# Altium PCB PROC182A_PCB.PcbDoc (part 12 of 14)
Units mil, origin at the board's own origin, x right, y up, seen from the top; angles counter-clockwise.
Board outline 3168.31 x 3700.79 mil, 8 copper layers (Top Layer, L2_GND1, L3_SIG1, L4_PWR1, L5_PWR2, L6_SIG2, L7_GND2, Bottom Layer), stack 58.1 mil thick; 580 components, 391 nets, 8314 pads, 4370 vias.
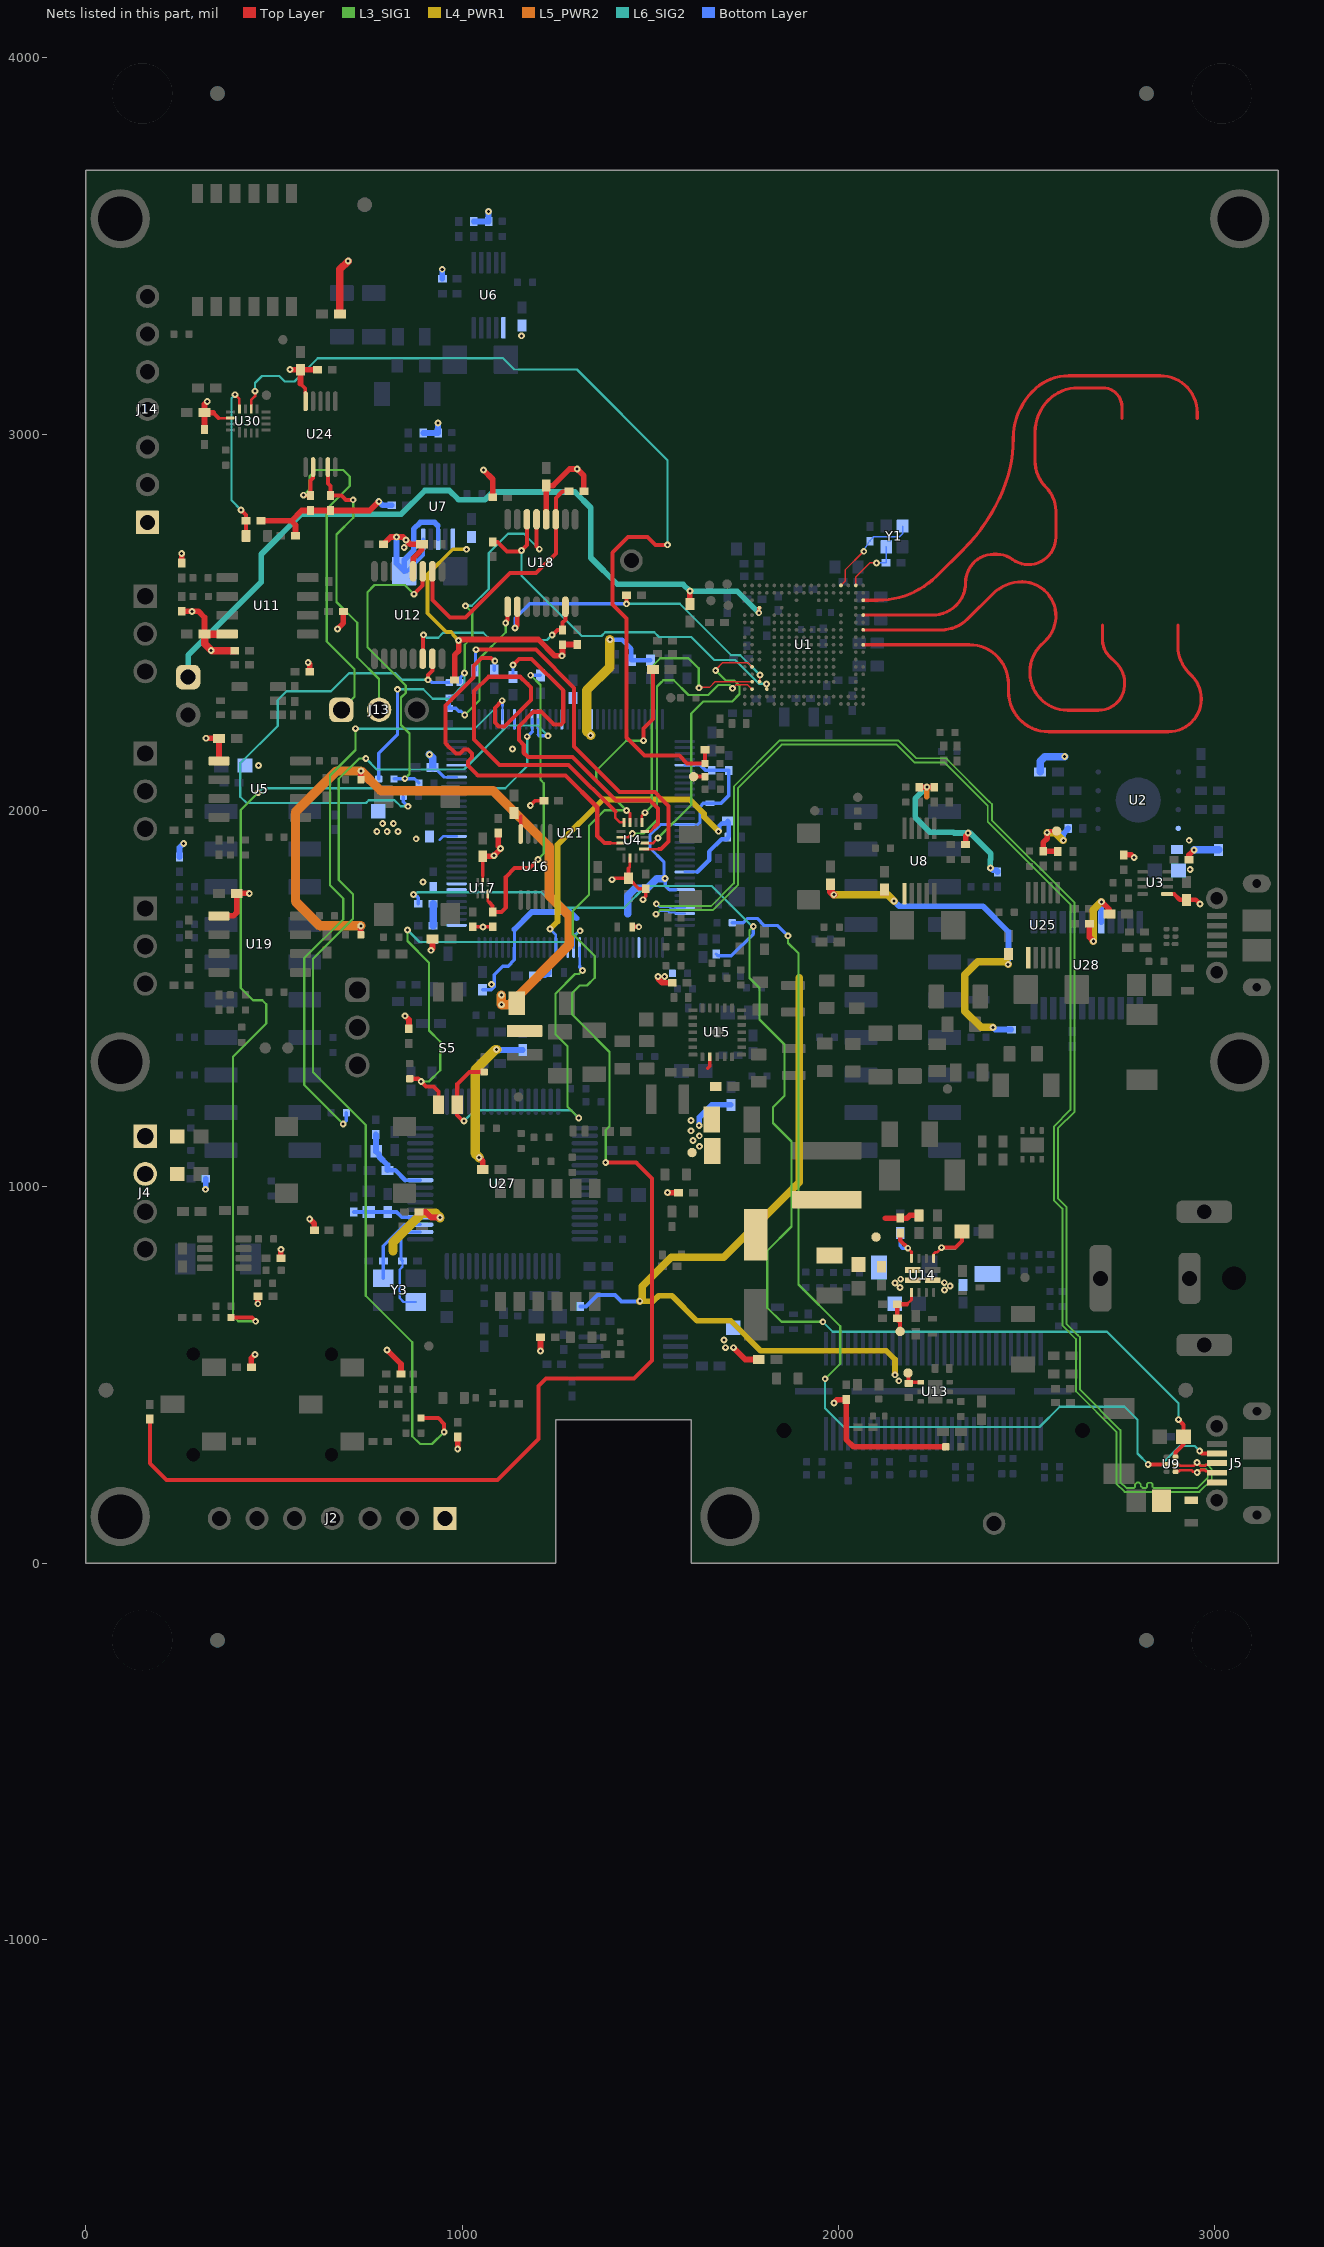
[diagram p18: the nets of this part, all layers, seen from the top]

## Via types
v1: diameter 13.77, hole 7, Top Layer to L2_GND1, tented both sides, 3444 vias
v2: diameter 18, hole 8, Top Layer to Bottom Layer, tented both sides, 911 vias
v3: diameter 13.77, hole 7, Top Layer to L2_GND1, tented top, 9 vias
v4: diameter 19.68, hole 7.87, Top Layer to Bottom Layer, 4 vias
v5: diameter 19.68, hole 7.87, Top Layer to Bottom Layer, tented both sides, 2 vias

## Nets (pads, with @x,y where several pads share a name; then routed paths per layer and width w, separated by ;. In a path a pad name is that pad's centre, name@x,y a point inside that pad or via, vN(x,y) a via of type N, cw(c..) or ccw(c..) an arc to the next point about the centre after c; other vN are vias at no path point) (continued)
SYS_RST_OUT: D9.1 R65.2 U30.12 | length 438.3
  Top Layer w7: v2(396.6,3104.72) 408.24,3093.09 U30.12@408.24,3066.34
  Top Layer w10.8: v2(412.68,2798.7) 426.03,2785.35 R65.2@426.03,2769.64 D9.1@426.03,2729.64
  L6_SIG2 w6: v2(396.6,3104.72) 387.21,3095.33 387.21,2824.17 v2(412.68,2798.7)
SYS_RST_OUT_SPIB_CS0_N: R146.1 R268.2 U30.10 | length 2497.9
  Top Layer w7: U30.10@439.74,3066.34 439.74,3090.48 450.04,3100.79 v2(450.04,3114.12)
  Top Layer w10.8: v2(1545.94,2706.01) 1545.67,2705.74 1513.3,2705.74 1492.75,2726.29 1440.94,2726.29 1399.63,2684.98 1399.63,2547.42 1436.63,2510.42 1436.63,2194.16 1484.92,2145.88 1576.88,2145.88 1597.72,2125.04 R268.2@1644.95,2125.04 1644.95,2160.46 R146.1@1645.54,2161.05
  L6_SIG2 w6: v2(450.04,3114.12) 450.04,3136.22 468.5,3154.67 514.07,3154.67 529.06,3139.68 554.81,3139.68 616.69,3201.57 1108.52,3201.57 1138.63,3171.47 1305.25,3171.47 1545.94,2930.78 v2(1545.94,2706.01)
TX1: U1.A3 | length 1302.5
  Top Layer w8.39: U1.A3@2065.55,2558.75 2104.39,2558.75 2104.45,2558.75 ccw(c2104.57,2780.67) 2202.13,2581.34 ccw(c2104.57,2780.67) 2261.61,2623.87 2332.43,2694.68 ccw(c1992.75,3034.6) 2436.7,2850.66 ccw(c2103.08,2988.89) 2464.2,2988.91 ; 2464.2,2988.94 cw(c2639.26,2989.49) 2515.1,3112.9 cw(c2611.78,3023.97) 2611.75,3155.33 2854.82,3155.33 ; 2854.86,3155.33 cw(c2854.83,3057.16) 2952.99,3057.16 2952.99,3042.46
TX2: U1.A5 | length 1302
  Top Layer w8.39: U1.A5@2065.55,2519.38 2249.63,2519.38 ccw(c2249.67,2608.28) 2312.64,2545.52 ccw(c2252.26,2605.7) 2337.51,2605.96 ; 2337.51,2606 cw(c2412.3,2605.95) 2412.3,2680.74 cw(c2419.35,2608.43) 2461.73,2667.45 2461.9,2667.32 ccw(c2504.65,2726.19) 2577.41,2726.19 2577.41,2795.68 ccw(c2488.67,2795.59) 2551.42,2858.34 cw(c2621.94,2928.86) 2522.21,2928.86 2522.21,3004.77 cw(c2642.88,3005.02) 2557.52,3090.31 cw(c2636.53,3011.27) 2636.53,3123.03 2701.8,3123.03 ; 2702.18,3123.02 cw(c2702.18,3072.21) 2752.99,3072.21 2752.99,3042.46
TX3: U1.A7 | length 1302.8
  Top Layer w8.39: U1.A7@2065.55,2480.01 2272.62,2480.01 ccw(c2272.62,2580.01) 2343.33,2509.3 2409.14,2575.11 cw(c2488.58,2495.74) 2487.84,2608.03 cw(c2487.9,2599.65) 2488.03,2608.03 cw(c2486.09,2516.69) 2547.32,2448.88 2545.91,2447.61 2537.63,2439.33 ccw(c2608.34,2368.62) 2520.31,2416.07 ccw(c2608.34,2368.62) 2508.44,2372.95 2508.44,2366.57 ccw(c2608.44,2366.57) 2510.83,2344.82 ccw(c2608.44,2366.57) 2608.44,2266.57 2690.85,2266.57 ; 2690.89,2266.57 ccw(c2690.94,2335.76) 2760.03,2339.57 2759.94,2341.29 ccw(c2691.24,2341.01) 2739.82,2389.58 2718.25,2411.15 cw(c2758.43,2451.33) 2701.6,2451.33 2701.6,2493
TX4: U1.A9 | length 1302.6
  Top Layer w8.39: U1.A9@2065.55,2440.64 2347.41,2440.64 cw(c2347.41,2336.43) 2451.62,2336.43 2451.62,2315.93 ccw(c2558.21,2315.93) 2558.21,2209.34 2875.9,2209.34 2875.95,2209.34 ccw(c2876.03,2296.96) 2938.61,2358.28 ; 2901.6,2493 2901.6,2436.72 ccw(c3001.6,2436.72) 2930.89,2366.01 2938.59,2358.31
UARTB_RX: J13.2 R275.1 U24.4 | length 766.4
  Top Layer w10.8: U24.4@643.35,2912.24 643.35,2868.98 649.99,2862.34 R275.1@649.99,2836.81 ; R275.1@650.21,2836.59 679.9,2836.59 690.9,2825.59 v2(710.5,2825.59)
  L3_SIG1 w6: v2(710.5,2825.59) 710.5,2777.81 665.97,2733.29 665.97,2554.06 721.39,2498.65 721.39,2407.64 779.43,2349.6 J13.2@779.43,2267.59
UARTB_TX: J13.1 R274.1 U24.2 | length 966.5
  Top Layer w10.8: v2(578.51,2837.87) 579.16,2837.23 594.55,2837.23 R274.1@597.17,2834.62 ; R274.1@597.17,2836.59 597.17,2876.67 604.01,2883.5 U24.2@604.01,2912.26
  L3_SIG1 w6: v2(578.51,2837.87) 595.34,2854.7 595.34,2889.02 611.13,2904.81 683.9,2904.81 701.46,2887.26 701.46,2862.43 640.38,2801.36 640.38,2449.39 714.25,2375.51 714.25,2302.42 J13.1@679.43,2267.59
USB_5V: C86.2 J5.1 L9.1
VBAT: J4.2 R32.1
VBUS_1_DETECT: C118.2 R236.1 R239.2 U21.1 | length 61.4
  Bottom Layer w8.7: C118.2@922.79,1693.47 C118.2@924.55,1695.23
  Bottom Layer w20: C118.2@922.79,1693.47 R236.1@922.79,1752.47
VCC_3V3: C34.1 C35.2 C36.1 C38.2 C40.1 C41.1 C52.2 C56.1 C57.1 C58.1 C59.1 C65.1 C104.1 C107.1 C109.2 C133.1 C135.1 C136.1 J2.1 J14.1 L14.2 R2.2 R5.2 R7.2 R8.2 R12.1 R14.2 R17.2 R22.2 R28.2 R44.2 R49.2 R50.1 R64.2 R65.1 R70.2 R82.2 R91.2 R94.1 R95.2 R97.2 R98.2 R99.2 R104.2 R105.2 R106.2 R107.2 R112.1 R115.1 R123.2 R127.2 R128.2 R135.2 R136.2 R138.2 R141.2 R142.1 R147.1 R149.1 R151.1 R154.2 R156.2 R157.2 R161.2 R163.2 R164.2 R165.2 R166.2 R172.2 R173.2 R200.1 R204.2 R207.2 R213.2 R253.2 R258.2 R262.2 R271.2 R274.2 R275.2 R277.2 R279.2 R283.1 R287.2 TP17.1 U2.8 U3.1 U4.14 U5.5 U6.6 U7.6 U7.8 U7.10 U8.6 U11.8 U12.12 U16.10 U17.5 U18.12 U19.5 U24.10 U25.6 U28.8 U30.14 | length 7795.7
  Top Layer w6.5: U17.5@1054.8,1809.55 1054.8,1826.78
  Top Layer w7: 353.08,3042.72 U30.14@384.62,3042.72 ; 1441.72,1845.84 1445.71,1849.83 U4.14@1445.71,1873.86
  Top Layer w8: 1054.8,1826.78 C52.2@1054.8,1878.55
  Top Layer w10: 570.67,3133.69 583.17,3121.18 583.17,3109.77 584.32,3108.62 U24.10@584.32,3087.46 ; R123.2@1028.35,1691.39 R138.2@1081.26,1691.39 ; U16.10@1155.59,1937.85 1155.59,1983.88 ; v2(1181.1,2013.78) 1193.57,2026.25 R95.2@1217.06,2026.25 ; v2(1398.42,1816.25) 1400.58,1816.25 1404.35,1820.02 C40.1@1441.72,1820.02 ; 1441.72,1845.84 C40.1@1441.72,1820.02 ; v2(1480.6,1763.15) 1480.6,1765.3 1487.66,1772.35 R5.2@1487.66,1792.41 1469.33,1792.41 C40.1@1441.72,1820.02 ; v2(2554.38,1941.12) 2556.54,1941.12 2561.07,1945.65 TP17.1@2579.58,1945.65 ; U3.1@2872.92,1778.17 2891.33,1778.17
  Top Layer w10.8: 338.66,3057.13 353.08,3042.72
  Top Layer w12: 2891.33,1778.17 2906.81,1762.7 C36.1@2924.66,1762.7 2949.49,1762.7 v2(2960.1,1752.09)
  Top Layer w15: R97.2@254.77,2529.42 v2@282.35,2529.42 ; R98.2@254.77,2657.7 254.77,2682.89 v2(255.07,2683.18) ; v2(282.56,2529.21) v2@282.35,2529.42 ; C65.1@315.62,2468.79 315.42,2468.99 315.42,2513.32 299.32,2529.42 v2@282.35,2529.42 ; R271.2@315.66,3012.1 C136.1@315.66,3057.1 ; v2(319.74,2192.12) 319.88,2191.99 354.05,2191.99 C38.2@354.18,2191.85 U5.5@354.18,2131.85 ; v2(322.86,3086.49) 315.66,3079.29 C136.1@315.66,3057.1 ; 338.66,3057.13 C136.1@315.68,3057.13 ; U19.5@354.01,1720.14 392.47,1720.14 401.26,1728.93 C109.2@401.26,1780.14 434.36,1780.14 v2(434.5,1780) ; R204.2@440.06,520.9 440.06,545.37 v2(449.8,555.12) ; v2(457.16,689.73) 457.42,689.99 457.42,709.08 R22.2@457.67,709.34 ; R65.1@465.4,2769.64 546.41,2769.64 ; R17.2@518.5,810.73 518.5,834.19 v2(518.57,834.26) ; v2(542.61,3171.73) 542.97,3171.37 570.31,3171.37 C135.1@570.67,3171.01 ; R64.2@557.48,2729.64 557.48,2758.57 546.41,2769.64 ; 570.67,3133.69 C135.1@570.67,3171.01 ; v2(591.03,2393.29) 591.03,2392.48 595.04,2388.47 R82.2@595.04,2369.21 ; v2(595.09,914.75) 607.39,902.45 607.39,886.97 607.46,886.9 R287.2@607.46,884.63 ; R253.2@615.67,3171.01 C135.1@570.67,3171.01 ; v2(668.89,2482.57) 684.58,2498.26 684.58,2526.44 R161.2@684.56,2528.79 ; v2(778.64,2821.3) 754.55,2797.22 R275.2@650.21,2797.22 R274.2@597.17,2797.22 573.98,2797.22 546.41,2769.64 ; R7.2@791.59,2707.74 810.53,2726.68 842.92,2726.68 851.01,2718.59 v2(851.1,2718.59) 862.11,2707.58 C41.1@892.99,2707.58 892.99,2693.18 869.69,2669.88 U12.12@869.69,2635.52 ; v2(800.64,566.66) 837.74,529.56 R207.2@837.74,503.14 ; v2(848.28,1454.6) 858.69,1444.19 R164.2@858.69,1420.46 ; R165.2@885.92,933.61 903.28,933.61 918.12,918.77 v2(941.29,918.77) ; v2(917.32,1628.63) 917.32,1629.44 921.46,1633.58 R213.2@921.46,1658.85 ; R8.2@979.95,2346.78 979.95,2413.12 990.66,2423.83 v2(990.66,2452.12) ; R28.2@988.19,335.63 R28.2@988.19,335.63 988.25,303.82 v2(988.3,303.76) ; v2@990.09,2452.69 v2(990.66,2452.12) ; v2(1045.47,1078.08) 1054.8,1068.75 R70.2@1054.8,1046.11 ; C52.2@1054.8,1878.55 1081.85,1878.55 1083.55,1880.24 v2(1084.36,1880.24) 1084.36,1880.93 1101.79,1898.36 1101.79,1899.86 1096.4,1905.26 R163.2@1096.4,1939.9 ; v2(1057.02,2904.62) 1081.36,2880.28 R127.2@1081.36,2832.49 ; v2(1208.11,564.42) R141.2@1208.07,600.82 ; U18.12@1223.27,2773.84 1223.27,2863.03 C107.1@1223.43,2863.19 1241.5,2863.19 1285.66,2907.34 v2(1305.73,2907.34) 1323.43,2889.64 R149.1@1323.43,2847.79 ; v2(1265.58,2411.26) 1245.7,2411.26 1202.51,2454.45 993.8,2454.45 991.47,2452.12 v2(990.66,2452.12) ; v2@1266.79,2413.33 1266.79,2440.45 1267.35,2441.03 R128.2@1306.31,2441.03 ; v2(1520.14,1558.91) 1520.71,1558.34 1520.71,1553 1531.3,1542.41 1544.97,1542.41 1545.31,1542.75 L14.2@1558.38,1542.75 ; v2(1545.45,985.09) 1560.29,985.09 1560.91,984.47 R172.2@1575.22,984.47 ; v2(1987.89,426.38) 1987.89,427.33 1995.6,435.04 R258.2@2020.2,435.04 2020.2,329.4 2039.8,309.8 R91.2@2284.82,309.8 ; R115.1@2214.61,2061.87 2214.8,2062.06 2234.24,2062.06 v2(2234.43,2062.26) ; v2@2234.25,2061.87 R107.2@2253.97,2061.87 ; R106.2@2337.61,1909.92 2337.61,1932.85 2344.35,1939.59 v2(2344.35,1940.4) ; v2@2554.56,1940.94 2554.56,1926.01 2543.66,1915.11 R142.1@2543.66,1891.83 2543.46,1891.62 R136.2@2582.83,1891.62 ; R135.2@2666.46,1699.68 2666.46,1663.59 v2(2677.26,1652.79) ; v2@2698.87,1757.66 2719.44,1737.08 C56.1@2719.44,1725.45 ; R151.1@2757.43,1882.19 2777.86,1882.19 2784.63,1875.41 v2(2785.44,1875.41) ; R283.1@2931.06,1869.68 2931.06,1881.8 v2(2944.81,1895.56)
  Top Layer w20: U11.8@375.62,2468.79 C65.1@315.62,2468.79 315.62,2443.36 v2(333.48,2425.5) 334.74,2424.24 R157.2@395.99,2424.24 ; R277.2@675.36,3319.65 675.36,3437.81 v2(697.24,3459.69) ; R262.2@1979.05,1804.31 1979.05,1784.89 v2(1987.54,1776.4)
  L5_PWR2 w15: 2234.43,2036.96 v2(2234.43,2062.26)
  L4_PWR1 w10: v2(990.66,2452.12) 976.55,2466.23 976.55,2468.45 970.69,2474.31 958.07,2474.31 908.07,2524.31 908.07,2626.93 975.31,2694.18 v2(1011.63,2694.18)
  L4_PWR1 w20: v2(1987.54,1776.4) 2130.61,1776.4 v2(2147.47,1759.53) ; v2(2410.16,1423.76) 2378.89,1423.76 2335.86,1466.79 2335.86,1564.17 2370.02,1598.32 2444,1598.32 v2(2450.79,1591.54) ; v2(2554.38,1941.12) 2576.02,1941.12 2596.2,1920.94 v2(2597.08,1920.94) ; v2(2677.26,1652.79) 2677.26,1736.62 v2(2698.3,1757.66)
  L4_PWR1 w25: 816.39,830.44 816.39,853.02 893.41,930.04 930.02,930.04 v2(941.29,918.77) ; v2(1045.47,1078.08) 1034.33,1089.22 1034.33,1310.79 1088.69,1365.16 1091.42,1365.16 v2(1091.54,1365.28)
  L6_SIG2 w15: v2(2234.43,2062.26) 2203.96,2031.79 2203.96,1981.53 2243.28,1942.21 2305.35,1942.21 2307.15,1940.4 v2(2344.35,1940.4) ; v2@2349.36,1941.23 2404.48,1886.11 2404.48,1871.11 2403.51,1870.14 v2(2403.51,1847.11)
  Bottom Layer w10: R200.1@852.95,2635.41 868.81,2651.26 896.69,2679.15 U7.10@896.69,2720.53 ; 935.32,2757.08 936.14,2756.26 936.14,2720.61 U7.8@936.06,2720.53
  Bottom Layer w15: R156.2@249.2,1876.82 249.2,1901.52 260.03,1912.35 v2(260.33,1912.35) ; v2(318.38,993.72) 318.65,994 318.65,1021.82 R166.2@318.93,1022.1 ; v2(778.64,2821.3) 788.76,2811.18 R104.2@813.05,2811.18 ; v2(825.71,2726.68) 825.71,2656.74 R200.1@846.26,2636.19 846.26,2666.04 871.16,2690.94 871.16,2747.75 889.03,2765.61 926.79,2765.61 935.32,2757.08 ; R105.2@896.69,3003.13 R112.1@936.06,3003.13 935.85,3003.34 v2(935.85,3029.84) ; v2(947.2,3437.99) 947.33,3437.85 947.33,3413.1 R2.2@947.46,3412.97 ; R14.2@1031.09,3564.92 R94.1@1070.46,3564.92 1070.26,3565.13 v2(1070.26,3591.63) ; v2(1091.54,1365.28) 1092.35,1365.28 1093.64,1363.99 1156.75,1363.99 R99.2@1161.06,1363.98 ; v2(2147.47,1759.53) 2161.16,1745.84 2383.62,1745.84 2451.64,1677.83 2451.64,1635.51 2450.79,1634.66 v2(2450.79,1591.54) ; v2(2403.51,1847.11) 2404.32,1847.11 2410.3,1841.13 2420.01,1841.13 2422.35,1838.79 R173.2@2422.35,1836.82 ; v2(2410.16,1423.76) 2410.62,1423.76 2416.22,1418.15 R12.1@2459.19,1418.15 ; v2(2597.08,1920.94) 2597.08,1934.19 2596.28,1934.99 2596.28,1937.12 2607.44,1948.28 2607.44,1950.25 R50.1@2609.78,1952.59 ; U28.8@2698.32,1703.39 v2(2698.3,1757.66)
  Bottom Layer w20: R44.2@2535.44,2102.59 2535.44,2131.08 2547.9,2143.55 v2(2600.75,2143.55) ; v2(2944.81,1895.56) 2945.03,1895.35 R49.2@3009.77,1895.35
  other v2: 1538.14,1558.91 1055.39,1690.93 2934.26,1843.64 1101.79,1899.05 2931.64,1920.9 459.18,2119.6 846.05,2698.8 1157.51,3261.37
VCC_12V: C30.1 C49.1 C54.1 C60.1 L1.2 R4.2 R9.1 TP7.1 U14.7 | length 92
  Top Layer w15: 2124.85,917.07 2181.72,917.07 2189.19,924.54 R4.2@2213.72,924.54
VCC_CAN_3V3: C72.2 L4.2 R69.2 R129.2 | length 1840.8
  Top Layer w15: R129.2@730.9,1670.14 v2(730.9,1693.46) ; R69.2@731.07,2081.85 v2(731.1,2105.19)
  L5_PWR2 w25: v2(730.9,1693.46) 622.61,1693.48 557.42,1758.68 557.42,1996.06 666.55,2105.19 v2(731.1,2105.19) 783.75,2052.54 1082.35,2052.54 1231.24,1903.64 1231.24,1773.35 1284.22,1720.37 1284.22,1642.49 1126.03,1484.29 v2(1104.85,1484.29) 1104.18,1484.96 v2(1104.18,1509.73)
VCC_XDS_3V3: C105.1 C106.2 C108.1 C113.2 C114.1 C115.1 C116.2 L7.1 R195.2 R196.2 R202.1 R231.2 R233.2 TP20.1 U13.1 U21.7 U21.8 U21.16 U21.26 U21.28 U21.39 U21.47 U21.51 U21.52 U21.69 U21.79 U21.90 U21.101 U21.113 U21.122 | length 4050.1
  Top Layer w10: C105.1@2186.43,478.03 2189.73,481.33 U13.1@2218.4,481.33
  Top Layer w10.8: TP20.1@2184.58,505.88 2186.43,504.03 C105.1@2186.43,478.03
  Top Layer w12: C108.1@1451.68,1690.92 1451.82,1691.06 1469.28,1691.06 v2(1469.42,1691.2)
  L4_PWR1 w15: v2(1471.95,696.59) 1508,696.59 1522.31,710.9 1557.54,710.9 1624.2,644.24 1713.87,644.24 1793.42,564.69 2127.04,564.69 2149.87,541.85 v2(2149.87,500.99)
  L4_PWR1 w20: v2(1471.95,696.59) 1478.7,703.34 1478.7,736.35 1555.06,812.7 1695.11,812.7 1895.31,1012.89 1895.31,1556.44
  L4_PWR1 w25: v2(1341.6,2199.82) 1330.74,2210.68 1330.74,2319.46 1392.63,2381.35 v2(1392.63,2454.02)
  Bottom Layer w6: 1542.21,1962.84 U21.79@1591.56,1962.84 ; U21.79@1591.66,1962.94 1625.68,1962.94 ; U21.69@1591.66,2120.42 1633.4,2120.36
  Bottom Layer w7: 940.54,1922.34 949.65,1931.45 U21.16@985.36,1931.45 ; 952.17,2088.93 U21.26@985.36,2088.93 ; U21.39@1138.9,2219.16 U21.39@1138.9,2242.47
  Bottom Layer w8: U21.113@1280.63,1636.17 1280.63,1680.3
  Bottom Layer w8.7: C106.2@937.12,2103.97 952.17,2088.93 ; U21.122@1138.9,1636.17 1138.9,1684.26 ; 1280.63,1680.3 1291.29,1690.95 ; v2@1536.24,1819.4 1536.24,1863.41 1499.11,1900.54 1499.11,1935.72 1526.23,1962.84 1542.21,1962.84 ; v2(1538.71,1819.4) 1540,1818.11 1540,1800.42 1550.65,1789.78 U21.90@1568.45,1789.78 ; 1625.68,1962.94 1632.04,1969.3 1632.04,2010.7 1640.58,2019.25 C114.1@1658,2019.25
  Bottom Layer w9: R233.2@1054.62,1524.36 1077.65,1524.36 1085.43,1532.14 1085.43,1563.79 1108.32,1586.68 1122.43,1586.68 1138.9,1603.16 U21.122@1138.9,1636.17
  Bottom Layer w10: L7.1@1313.51,682.66 1329.36,682.66 1359.46,712.76 1406.49,712.76 1423.74,695.51 1470.87,695.51 v2(1471.95,696.59) ; 1633.4,2120.36 1646.78,2106.97 R231.2@1663.56,2106.97 1708.2,2106.96 1708.21,2039.85 1687.61,2019.25 C114.1@1658,2019.25
  Bottom Layer w12: v2(1392.63,2454.02) 1425.34,2454.02 1449.62,2429.74 R196.2@1449.62,2399.25 R195.2@1500.19,2399.25
  Bottom Layer w15: 1138.9,1684.26 1184.98,1730.35 1287.6,1730.35 1304.03,1713.91
  Bottom Layer w20: v2(913.04,2149.22) 921.53,2140.74 C106.2@921.53,2114.19 ; 1439.63,1725.39 1439.63,1773.25 1459.91,1793.53 1491.7,1793.53 1516.68,1818.51 1537.81,1818.51 v2(1538.71,1819.4)
  other v2: 2160.05,485 1077.76,1538.38 896.07,1810.38 877.94,1925.03 1134.18,2163.28
VDDC_1: C124.1 C125.2 C126.2 C127.1 U21.87 U21.115 | length 1177.5
  L4_PWR1 w15: v2(1233.78,1685.06) 1253.55,1704.83 1253.55,1909.06 1374.02,2029.53 1604.58,2029.53 1615.32,2018.79 1642.69,1991.42 1642.69,1983.63 v2(1681.38,1944.95)
  Bottom Layer w7: v2(1233.78,1685.06) 1249.14,1669.7 U21.115@1249.14,1636.17 ; 1245.8,1599.6 1249.14,1602.94 U21.115@1249.14,1636.11 ; U21.87@1591.66,1836.96 1625.07,1836.96
  Bottom Layer w12: C126.2@1193.75,1560.97 1221.46,1560.97 1224.8,1564.32 1229.3,1564.32 1230.8,1565.82 1230.8,1583 1247,1599.19 ; 1625.07,1836.96 1655.98,1867.87 1655.98,1891.07 1689.13,1924.22 1703.06,1924.22 1705.92,1927.08 C124.1@1705.92,1929.29 1708.7,1932.07 1708.7,1969.34 C125.2@1705.63,1972.41 1699.82,1966.6 1690.84,1966.6 1682.53,1958.28 1682.53,1946.1 v2(1681.38,1944.95)
VIN1_PR1: R9.2 R23.2 U14.6 | length 136.9
  Top Layer w7: v2(2184.16,837.42) 2193.8,827.77 U14.6@2193.8,810.34
  Top Layer w10.8: R9.2@2163.93,877.7 2163.93,857.64 v2(2184.16,837.42)
  Bottom Layer w8.7: R23.2@2163.93,877.7 2163.93,843.13 2169.64,837.42 v2(2184.16,837.42)
VIN2_CP2: R36.1 R75.2 U14.3 | length 213.1
  Top Layer w7: U14.3@2252.86,810.34 2252.86,822.26 2256.96,826.36 2261,826.36 v2(2273.43,838.79)
  Top Layer w10.8: v2(2273.43,838.79) 2310.38,838.79 2328.37,856.78 R36.1@2328.37,881.48
  Bottom Layer w8.7: v2(2273.43,838.79) 2310.38,838.79 2327.69,856.1 R75.2@2327.69,881.32
VOUT_STATUS: R27.2 R73.1 TP13.1 U14.9 | length 138.3
  Top Layer w7: 2182.22,688.47 2193.8,700.04 U14.9@2193.8,719.79
  Top Layer w10.8: R27.2@2156.28,651.13 R27.2@2155.94,651.47 ; TP13.1@2163.76,616.28 2163.76,639.42 2155.94,647.24 R27.2@2155.94,651.47 ; 2182.22,688.47 R73.1@2155.94,688.47 R27.2@2155.94,651.47
VPHY_FTDI: C141.1 C142.2 L2.2 U27.4 | length 182.4
  Bottom Layer w10: L2.2@712.28,933.67 C141.1@752.28,933.67 825.81,933.67 839.74,919.73 U27.4@888.86,919.73
VPLL_FTDI: C145.1 C146.2 L3.2 U27.9 | length 206.3
  Bottom Layer w10: 848.94,1018.14 U27.9@888.88,1018.14
  Bottom Layer w12: C146.2@801.58,1044.27 822.81,1044.27 848.94,1018.14
  Bottom Layer w15: L3.2@770.99,1139.23 771.33,1138.89 C145.1@771.33,1093.93 ; C145.1@771.67,1094.58 779.91,1086.33 779.91,1080.25 801.58,1058.58 C146.2@801.58,1044.27
VPP_1P7: C31.1 P1.1 U1.R4 | length 2068.7
  Top Layer w10: v2(1788.24,2525.32) 1788.24,2537.34 U1.R4@1789.96,2539.06
  Top Layer w15: C31.1@1605.14,2557.21 v2(1605.14,2583.05)
  L6_SIG2 w15: P1.1@272.13,2354.41 272.13,2412.59 466.41,2606.86 466.41,2680.97 572.9,2787.47 838.23,2787.47 901.1,2850.35 965.85,2850.35 990.25,2825.95 1060.64,2825.95 1081.03,2846.33 1299.88,2846.33 1341.7,2804.51 1341.7,2671.58 1412.33,2600.96 1528.36,2600.96 1587.23,2600.96 v2(1605.14,2583.05) 1730.51,2583.05 v2(1788.24,2525.32)
VSYS_IN: C50.1 C61.1 C62.1 C64.1 C74.1 C137.1 C154.2 J4.1 R30.1 R31.1 R145.2 R155.2 R174.1 TP15.1 U14.1 U14.8 U15.9 | length 231.9
  Top Layer w9: 1652.69,1315.44 1658.11,1320.85 U15.9@1658.11,1345.81
  Top Layer w15: v2(1720.8,572.97) 1752.01,541.76 R174.1@1788.06,541.76
  Bottom Layer w15: v2(1629.89,1163.54) 1629.89,1184.82 1663.12,1218.05 R145.2@1713.97,1218.05
  other v2: 1700.02,573.1 1695.87,593.5 2281.56,726.31 2163.56,733.06 2296.68,736.73 2150.09,745 2280.9,745.72 2165,755.09 1630.81,1107.9 1613.5,1123.73 1630,1135.9 1607.89,1149.17 1607.89,1176.8 773.37,1944.39 801.01,1944.49 829.57,1944.73 788.87,1965.68 817.19,1965.92
WU_REQ_IN: R267.2 TP8.1 | length 30
  Top Layer w10.8: TP8.1@1614.95,2090.04 R267.2@1644.95,2090.04
XDS_DCA_LP_FTDI_UARTA_RX: R147.2 U12.6 U18.7 | length 525.1
  Top Layer w10.8: U12.6@895.28,2403.24 896.43,2404.38 896.43,2465.9 v2(897.57,2467.05) ; v2@1240.14,2466.71 1253.26,2479.83 R147.2@1266.78,2479.83 1266.78,2499.12 1274.45,2506.79 U18.7@1274.45,2541.56
  L6_SIG2 w6: v2(897.57,2467.05) 898.05,2467.05 905.94,2459.15 936.47,2459.15 949.44,2472.12 1056.28,2472.12 1075.1,2453.3 1225.81,2453.3 v2@1239.05,2466.54
  other v2: 1239.21,2466.71
XDS_DCA_LP_FTDI_UARTA_TX: R149.2 U12.10 U18.11 | length 683.7
  Top Layer w10.8: U12.10@920.87,2635.52 920.87,2559.35 967.23,2512.99 1009.46,2512.99 1127.44,2630.98 1196.75,2630.98 1248.86,2683.09 U18.11@1248.86,2773.84 1248.86,2830.63 1266.02,2847.79 R149.2@1284.06,2847.79
XDS_DCA_TCK: U1.T12 U4.2 | length 771.5
  Top Layer w4: v2(1673.66,2372.08) 1673.66,2374.07 1692.64,2393.05 1693.09,2393.05 1758.87,2392.99 U1.T12@1770.28,2381.58
  Top Layer w7: U4.2@1485.24,1913.39 1506.97,1913.39 v2(1520.46,1926.88)
  L3_SIG1 w6: v2@1520.51,1926.88 1608.57,2014.93 1608.57,2023.03 1608.57,2165.93 1608.57,2257.67 1640.92,2290.03 1717.74,2290.03 1737.18,2309.47 1737.18,2331.17 1723.45,2344.91 1700.83,2344.91 v2(1673.66,2372.08)
XDS_DCA_TDI: U1.T14 U4.5 | length 769.8
  Top Layer w4: v2(1629.52,2326.08) 1630.58,2327.14 1656.89,2327.14 1672.04,2342.29 1683.85,2342.29 U1.T14@1770.28,2342.21
  Top Layer w7: U4.5@1477.36,1968.51 1477.36,1986.61 1484.99,1994.24 v2(1486.12,1994.24)
  L3_SIG1 w6: v2(1486.12,1994.24) 1503.94,2012.06 1503.94,2382.17 1526.34,2404.57 1601.67,2404.57 1628.5,2377.74 1628.5,2327.1 v2(1629.52,2326.08)
XDS_DCA_TDO_SOP0: R93.1 R203.1 U4.7 | length 3978.7
  Top Layer w7: v2(1436.74,2000.32) 1438.29,2000.32 1445.87,1992.74 U4.7@1445.87,1968.51
  Top Layer w10.8: R203.1@170.45,383.1 170.45,265.95 214.93,221.46 1094.25,221.46 1202.76,329.97 1202.76,471.53 1222.37,491.14 1456.91,491.14 1504.92,539.15 1504.92,1022.9 1462.56,1065.26 v2(1381.3,1065.26) v2@1381.3,1066.48 ; v2(1481.78,2185.74) 1481.78,2218.18 1506.76,2243.17 R93.1@1506.76,2374.99
  L3_SIG1 w6: v2(1381.3,1065.26) 1381.3,1151.54 1391.3,1161.54 1391.3,1358.6 1352.83,1397.06 1352.83,1397.6 1292.4,1458.03 1292.4,1515.34 1312.29,1535.23 1331.76,1535.23 1352.11,1555.57 1352.11,1613.6 1293.72,1671.99 1293.72,1732.9 1336.85,1776.03 1336.85,1959.63 1378.16,2000.93 v2@1436.12,2000.93 ; v2(1436.74,2000.32) 1356,2081.06 1356,2105.9 1435.83,2185.74 v2(1481.78,2185.74)
XDS_DCA_TMS: U1.T15 U4.10 | length 768.3
  Top Layer w4: v2(1718.58,2324.82) 1718.58,2325.22 1727.3,2333.94 1758.87,2333.94 U1.T15@1770.28,2322.53
  Top Layer w7: U4.10@1422.24,1929.13 1441.93,1929.13 v2(1452.18,1939.38)
  L3_SIG1 w6: v2(1452.18,1939.38) 1452.31,1939.25 1481.75,1939.25 1517.54,1975.03 1517.54,2329.68 1528.36,2340.5 1534.09,2346.23 1562.24,2346.23 1601.71,2306.75 1654.05,2306.75 1680.61,2333.31 1710.09,2333.31 v2(1718.58,2324.82)
XDS_FTDI_DCA_RS232_RX: R255.1 U1.R14 U18.2 | length 873
  Top Layer w4: U1.R14@1789.96,2342.21 1790.52,2342.77 1790.52,2359.77 v2(1791.07,2360.32)
  Top Layer w10.8: v2@1140.08,2485.13 v2(1140.25,2485.3) 1146.5,2491.55 U18.2@1146.5,2541.56 ; v2@1436.82,2547.2 v2(1436.82,2549.19) R255.1@1436.82,2572.49
  L6_SIG2 w6: v2(1436.82,2549.19) 1578.22,2549.19 1714.77,2412.64 1738.75,2412.64 v2(1791.07,2360.32)
  Bottom Layer w8.7: v2(1140.25,2485.3) 1140.25,2510.05 1179.39,2549.19 v2(1436.82,2549.19)
XDS_FTDI_DCA_RS232_TX: R256.1 U1.P15 U18.14 | length 1036.6
  Top Layer w4: v2(1808.45,2336.4) 1809.05,2335.8 1809.05,2323.13 U1.P15@1809.65,2322.53
  Top Layer w10.8: R256.1@1081.26,2713.87 1094.02,2713.87 1119.66,2688.23 1153.29,2688.23 1155.65,2690.59 v2(1157.6,2690.59) 1172.09,2705.08 U18.14@1172.09,2773.84
  L6_SIG2 w6: v2(1157.6,2690.59) 1157.6,2623.91 1317.62,2463.9 1370.08,2463.9 1380.19,2474.02 1510.08,2474.02 1523.02,2461.08 1608.87,2461.08 1669.68,2400.27 1725.16,2400.27 1725.73,2400.27 1789.03,2336.97 1807.88,2336.97 v2(1808.45,2336.4)
XDS_NRST: R126.2 R138.1 U17.3 | length 815
  Top Layer w6.5: U17.3@1068.58,1778.05 1068.58,1759.59 1072.95,1755.22
  Top Layer w10.8: 1072.95,1755.22 1081.26,1746.91 R138.1@1081.26,1730.76 1104.36,1730.76 1115.98,1742.38 1115.98,1823.81 1139.7,1847.54 1179.03,1847.54 v2(1201.74,1870.25)
  L3_SIG1 w6: v2(1182.07,2359.47) 1208.06,2333.48 1208.06,2081.89 1217.12,2072.83 1217.12,1885.63 v2(1201.74,1870.25)
  Bottom Layer w8.7: v2(1182.07,2359.47) 1207.59,2359.47 R126.2@1208.2,2358.86
XDS_RS232_RX: R24.2 R188.1 U18.1 | length 410.6
  Top Layer w10.8: v2(1115.84,2498.57) 1115.84,2500.52 1120.91,2505.59 U18.1@1120.91,2541.56
  L3_SIG1 w6: v2(1006.98,2254.16) 1045.95,2293.14 1045.95,2404.06 1115.84,2473.95 v2(1115.84,2498.57)
  Bottom Layer w8.7: R24.2@966.13,2299.53 R188.1@966.13,2271.53 983.24,2271.53 990.67,2264.1 997.04,2264.1 v2(1006.98,2254.16)
XDS_RS232_TX: R26.2 R181.1 U18.13 | length 1148.3
  Top Layer w10.8: U18.13@1197.68,2773.84 1197.68,2701.4 v2@1204.77,2694.31
  L3_SIG1 w6: v2(1006.41,2365.25) 1007.24,2366.08 1007.24,2440.42 1027,2460.18 1027,2525.51 v2(1008.65,2543.86)
  L6_SIG2 w6: v2(828.66,2322.23) 896.59,2322.23 922.05,2296.77 967.04,2296.77 1006.41,2336.13 v2(1006.41,2365.25) ; v2(1008.65,2543.86) 1025.54,2543.86 1070.49,2588.82 1070.49,2684.38 1121.6,2735.48 1163.93,2735.48 v2(1204.94,2694.48)
  Bottom Layer w8.7: R26.2@778.54,2083.94 778.54,2152.37 828.51,2202.35 v2@828.51,2322.07 ; R181.1@994.75,2340.16 995.68,2341.08 995.68,2354.52 v2(1006.41,2365.25)
XDS_SCL: R199.2 S5.3 U21.112 | length 1136.1
  Top Layer w10.8: R199.2@860.53,1287.52 883.42,1287.52 890.53,1280.4 v2(891.37,1280.4) 904.37,1267.41 923.73,1267.41 937.08,1254.06 S5.3@937.08,1218.36
  L3_SIG1 w6: v2(854.63,1682.86) 854.63,1653.26 912.19,1595.7 912.19,1415.6 941.74,1386.04 941.74,1310.01 912.19,1280.46 891.43,1280.46 v2(891.37,1280.4)
  L6_SIG2 w6: v2(854.63,1682.86) 886.86,1650.63 1283.68,1650.63 v2(1313.72,1680.67)
  Bottom Layer w7: U21.112@1296.38,1636.17 1296.38,1666.55 1310.5,1680.67 v2(1313.72,1680.67)
XDS_SDA: R197.2 S5.4 U21.111 | length 1034.6
  Top Layer w10.8: v2(1004.83,1175.09) 1003.45,1176.47 1001.32,1176.47 986.92,1190.86 986.92,1218.21 S5.4@987.08,1218.36 987.08,1273.15 1019.59,1305.66 R197.2@1058.48,1305.66
  L3_SIG1 w6: v2(1309.83,1183.38) 1309.83,1183.46 1279.87,1213.42 1279.87,1373.89 1247.95,1405.81 1247.95,1513.53 1299.96,1565.54 1310.56,1565.54 v2(1320.11,1575.09)
  L6_SIG2 w6: v2(1004.83,1175.09) 1033.26,1203.52 1289.77,1203.52 1309.83,1183.46 v2(1309.83,1183.38)
  Bottom Layer w6: 1312.19,1586.11 U21.111@1312.19,1636.17
  Bottom Layer w8.7: 1312.19,1586.11 1312.19,1583.44 1320.11,1575.52 v2(1320.11,1575.09)
XDS_SOP0: R43.1 U21.42 | length 2497.7
  Top Layer w10.8: R43.1@386.3,653.31 441.38,653.31 v2(451.69,643)
  L3_SIG1 w6: v2(451.69,643) 405.23,643 391.42,656.81 391.42,1346.04 479.49,1434.11 479.49,1485.29 468.84,1495.94 444.6,1495.94 411.9,1528.64 411.9,2001.47 456.9,2046.47 v2@456.9,2047.15
  L6_SIG2 w6: v2(457.78,2047.35) 469.87,2059.44 1114.34,2059.44 1172.99,2118.08 v2(1172.99,2196.35)
  Bottom Layer w6: 1186.15,2209.57 U21.42@1186.15,2242.47
  Bottom Layer w8.7: v2(1172.99,2196.35) 1172.99,2196.41 1186.15,2209.57
XDS_SOP1: R67.1 U21.43 | length 2828.8
  Top Layer w10.8: R67.1@891.14,386.19 936.65,386.19 952.32,370.52 v2(952.32,349.3)
  L3_SIG1 w6: v2(744.2,2138.24) 726.38,2138.24 672.36,2084.21 672.36,1815.54 710.33,1777.56 710.33,1712.78 604.13,1606.57 604.13,1304.44 744.05,1164.51 744.05,711.22 867.78,587.48 867.78,337.93 888.78,316.93 919.95,316.93 v2(952.32,349.3)
  L6_SIG2 w6: v2@744.37,2138.08 773.39,2109.05 1004.71,2109.05 1121.52,2225.86 1200.81,2225.86 v2(1228.06,2198.6)
  Bottom Layer w6: 1201.89,2201.81 1201.89,2202.62 1202.2,2202.92 1202.2,2242.17 U21.43@1201.89,2242.47
  Bottom Layer w8.7: 1201.89,2201.81 1205.1,2198.6 v2(1228.06,2198.6)
XDS_TCK: R122.2 U4.1 | length 999.4
  Top Layer w7: U4.1@1483.27,1897.64 1523.35,1897.64 1523.43,1897.73
  Top Layer w10.8: v2(1036.81,2427.51) 1040.01,2427.51 1040.14,2427.64 1195.8,2427.64 1297.51,2325.93 1297.51,2169.81 1418.54,2048.78 1512.22,2048.78 1528.36,2032.65 1548.41,2012.59 1548.41,1917.38 1528.76,1897.73 1523.43,1897.73
  Bottom Layer w8.7: R122.2@1035.35,2372.28 1035.57,2372.49 1035.57,2426.27 v2(1036.81,2427.51)
XDS_TDI: R125.2 U4.4 | length 1018.1
  Top Layer w7: U4.4@1485.24,1944.88 1500.31,1944.88 1511.57,1956.15
  Top Layer w10.8: v2(1135.15,2386.97) 1150.57,2402.39 1184.67,2402.39 1268.7,2318.36 1268.7,2234.87 1262.91,2229.08 1243.49,2229.08 1210,2262.58 1190.05,2262.58 1150.59,2223.12 1150.59,2187.07 1163.71,2173.95 1163.71,2153.52 1174.58,2142.65 1293.66,2142.65 1409.13,2027.18 1499,2027.18 1520.38,2005.8 1520.38,1964.96 1511.57,1956.15
  Bottom Layer w8.7: v2(1135.15,2386.97) 1135.23,2386.89 1135.23,2355.12 R125.2@1135.31,2355.04
XDS_TDO: R232.2 U4.8 U21.37 | length 2718.5
  Top Layer w7: 1406.99,1997.02 1406.99,1980.72 1419.2,1968.51 U4.8@1430.12,1968.51
  Top Layer w10.8: v2(1106.5,2291.88) 1087.42,2272.8 1087.42,2233.44 1097.28,2223.58 1113.06,2223.58 1183.12,2293.63 1183.12,2326.92 1172.96,2337.07 1172.79,2337.07 1154.43,2355.44 1069.51,2355.44 1031.16,2317.09 1031.16,2188.97 1099.09,2121.05 1282.95,2121.05 1406.99,1997.02
  L3_SIG1 w6: v2(684.04,1167.44) 580.82,1270.66 580.82,1608.41 683.86,1711.45 683.86,1766.6 649.06,1801.41 649.06,2092.95 716.97,2160.86 v2(716.97,2217.49)
  L6_SIG2 w6: v2(716.97,2217.49) 1033.34,2217.49 1106.5,2290.65 v2(1106.5,2291.88)
  Bottom Layer w6: U21.37@1107.41,2242.47 1107.41,2278.43 1107.51,2278.53
  Bottom Layer w8.7: v2(684.04,1167.44) 692.35,1175.74 R232.2@692.35,1197.45 ; v2(1106.5,2291.88) 1107.51,2290.87 1107.51,2278.53
XDS_TMS: R124.2 U4.11 | length 1000.6
  Top Layer w7: 1393.61,1913.39 U4.11@1422.24,1913.39
  Top Layer w10.8: v2(1086.89,2397.03) 1085.44,2397.03 1076.71,2405.76 1051.54,2405.76 1029.76,2383.97 1029.76,2353.46 955.3,2279 955.3,2179.84 959.12,2176.02 983.22,2151.92 994.11,2151.92 1004.79,2162.6 1015.68,2162.6 1026.57,2151.71 1026.57,2140.82 1015.89,2130.14 1015.89,2119.25 1037.67,2097.47 ; 1393.61,1913.39 1378.02,1913.39 1358.99,1932.42 1358.99,2008.81 1274.14,2093.66 1041.48,2093.66 ; 1037.67,2097.47 1041.48,2093.66 ; 1037.67,2097.47 1041.49,2093.65
  Bottom Layer w8.7: R124.2@1085.33,2372.28 1085.39,2372.33 1085.39,2388.72 1085.44,2388.77 1085.44,2395.58 v2(1086.89,2397.03)
XDS_UARTA_RX: R24.1 R290.1 U12.7 | length 1350
  Top Layer w10.8: v2(909.53,2347.27) 909.53,2360.24 920.87,2371.58 U12.7@920.87,2403.24
  L6_SIG2 w6: v2(856.43,2011.43) 836.71,2011.43 820.54,2027.6 752.14,2027.6 744.61,2020.07 427.72,2020.07 410.79,2037 410.79,2125.65 509.95,2224.81 509.95,2293.71 533.33,2317.1 651.54,2317.1 699.38,2364.94 823.18,2364.94 840.85,2347.27 v2(909.53,2347.27)
  Bottom Layer w8.7: R290.1@843.92,2038.44 843.92,2023.02 855.51,2011.43 v2(856.43,2011.43) ; v2(909.53,2347.27) 911.9,2347.27 918.84,2340.32 R24.1@966.57,2340.32
XDS_UARTA_TX: R26.1 R190.1 U12.11 | length 839.9
  Top Layer w10.8: v2(872.21,2574.85) 895.28,2597.92 U12.11@895.28,2635.52
  L3_SIG1 w6: v2(847.81,2084.68) 860.13,2097 860.13,2204.98 837.8,2227.31 837.8,2300.22 850.02,2312.44 850.02,2332.38 748.49,2433.92 748.49,2580.19 767.49,2599.2 847.87,2599.2 v2(872.21,2574.85)
  Bottom Layer w8.7: R26.1@818.89,2083.94 819.63,2084.68 v2(847.81,2084.68) 873.51,2084.68 879.51,2078.67 880,2078.67 R190.1@885,2073.67
XDSET_1_DM: J5.2 U9.4 U21.93 | length 3819.6
  Top Layer w7.5: U9.4@2895.33,243.53 2897.36,245.56 2905.05,245.56 2907.11,247.62 2938.02,247.62 2942.08,243.56 2950.83,243.56 v2(2952.84,241.55) 2955.68,241.55 2961.93,247.8 2973.4,247.8 2976.32,244.88 3001.09,244.88 J5.2@3005.21,240.76
  L3_SIG1 w5: v2(1515.88,1752.3) 1519.4,1752.3 1525.25,1746.44 1661.95,1746.44 1721.85,1806.34 1721.85,2063.92 1844.11,2186.17 2158.8,2186.17 2206.01,2138.96 2285.75,2138.96 2292.14,2132.58 2400.9,2023.81 2407.29,2017.42 2407.29,1974.79 2627.09,1754.99 2627.09,1200.19 2582.85,1155.95 2582.85,969.73 2605.42,947.16 2605.42,636.71 2635.83,606.3 2641.81,600.32 2641.81,461.51 2749.02,354.3 2749.02,215.9 2764.34,200.58 2785.09,200.58 2788.02,203.5 2788.02,209.83 2792.67,214.48 2799.02,214.48 2803.02,210.48 2803.02,205.48 2807.92,200.58 2817.09,200.58 2820.02,203.5 2820.02,211.26 2822.95,214.19 2831.09,214.19 2834.02,211.26 2834.02,203.58 2837.02,200.58 2954.31,200.58 2980.78,227.04 2980.78,246.02 2976.15,250.65 2962.18,250.65 2955.77,244.24 2955.77,241.55 v2(2952.84,241.55)
  Bottom Layer w6: v2(1515.88,1752.3) 1517.11,1752.3 1525.4,1744.01 1550.71,1744.01 1554.62,1740.1 1565.16,1740.1 1567.53,1742.47 U21.93@1591.66,1742.47
XDSET_1_DP: J5.3 U9.5 U21.94 | length 3821
  Top Layer w7.5: U9.5@2895.33,263.22 2897.36,261.19 2905.05,261.19 2907.11,259.12 2943.12,259.12 v2(2952.27,268.28) 2961.24,259.3 2973.4,259.3 2976.32,262.22 3001.09,262.22 J5.3@3005.21,266.35
  L3_SIG1 w5: v2(1515.24,1724.71) 1526.07,1735.54 1666.47,1735.54 1732.75,1801.83 1732.75,2059.4 1848.62,2175.27 2154.28,2175.27 2201.5,2128.06 2281.24,2128.06 2396.39,2012.91 2396.39,1970.27 2616.19,1750.47 2616.19,1204.7 2571.95,1160.46 2571.95,965.22 2594.52,942.65 2594.52,632.19 2630.91,595.81 2630.91,457 2738.12,349.79 2738.12,211.38 2759.82,189.68 2785.09,189.68 2800.07,189.68 2958.83,189.68 2991.68,222.53 2991.68,250.53 2980.67,261.55 2961.8,261.55 2955.07,268.28 v2(2952.27,268.28)
  Bottom Layer w6: v2(1515.24,1724.71) 1516.46,1724.71 1524.75,1733.01 1546.15,1733.01 1550.06,1729.1 1565.16,1729.1 1567.53,1726.72 U21.94@1591.66,1726.72
XDSET_1_ID: J5.4 R170.2 U9.2 | length 2780
  Top Layer w10.8: v2@2822.73,263.22 U9.2@2871.71,263.22 ; v2(2959.62,298.44) 2959.62,297.4 2965.08,291.94 J5.4@3005.21,291.94
  L3_SIG1 w6: v2(1866.03,1667.13) 1866.03,1648.26 1893.61,1620.69 1893.61,741 2004.66,629.95 2004.66,530.58 v2(1964.45,490.36)
  L6_SIG2 w6: v2(1964.45,490.36) 1963.76,489.68 1963.76,412.07 2013.65,362.19 2533.94,362.19 2587.81,416.06 2759.61,416.06 2794.14,381.53 2794.14,291.6 v2(2822.73,263.01) 2857.84,263.01 2906.35,311.52 2946.54,311.52 v2(2959.62,298.44)
  Bottom Layer w8.7: R170.2@1717.62,1701.9 1746.76,1701.9 1758.17,1713.3 1783.82,1713.3 1802.55,1694.58 1838.58,1694.58 1852.13,1681.04 v2(1866.03,1667.13)
XDSET_1_VBUS: R1.1 R169.2 R236.2 U9.6 | length 3636.2
  Top Layer w10.8: U9.6@2895.33,282.9 2895.33,295.18 2916.43,316.28 R1.1@2916.43,336.42 2916.43,368.31 v2(2902.88,381.86)
  L3_SIG1 w6: v2(1773.47,1691.95) 1763.67,1682.16 1763.67,1554.93 1790.24,1528.36 1790.24,1444.71 1856.25,1378.69 1856.25,1242.08 1825.79,1211.62 1825.79,1169.73 1874.84,1120.68 1874.84,894.69 1810.75,830.59 1810.75,679.36 1848.38,641.72 v2(1958.35,641.72)
  L6_SIG2 w6: v2(871.01,1776.85) 874.25,1776.85 878.8,1781.39 879.92,1781.39 881.39,1782.86 1210.54,1782.86 1235.59,1757.82 1260.21,1757.82 1276.28,1741.75 1430.92,1741.75 1488.57,1799.4 1527.78,1799.4 1663.11,1799.4 1770.56,1691.95 v2(1773.47,1691.95) ; v2(1958.35,641.72) 1984.89,615.19 2713.03,615.19 2902.88,425.34 v2(2902.88,381.86)
  Bottom Layer w8.7: v2(871.01,1776.85) 873.52,1776.85 878.08,1772.29 880.23,1772.29 883.49,1769.04 R236.2@883.49,1752.53 ; R169.2@1674.64,1618.9 1679.57,1613.97 1715.6,1613.97 1773.47,1671.84 v2(1773.47,1691.95)
XI_FTDI: C148.1 U27.2 Y3.1 | length 270.5
  Bottom Layer w6: C148.1@841.89,803.24 841.89,788.85 834.02,780.98 834.02,704.88 844.56,694.34 Y3.1@877.11,694.34
  Bottom Layer w8.7: C148.1@841.89,803.24 837.74,807.39 837.74,865.77 852.32,880.34 U27.2@888.88,880.34
XO_FTDI: C147.1 U27.3 Y3.3 | length 207.5
  Bottom Layer w8.7: Y3.3@790.5,757.33 C147.1@790.5,802.99 ; C147.1@790.75,803.24 790.58,803.4 790.58,843.22 847.39,900.03 U27.3@888.88,900.03
XTALM: C33.2 U1.B1 Y1.1 | length 161.1
  Top Layer w4: U1.B1@2045.87,2598.12 2045.87,2620.8 2082.95,2657.88 v2(2100.91,2657.88)
  Bottom Layer w4: v2(2100.91,2657.88) 2125.63,2657.88 C33.2@2126.29,2658.54 2126.29,2700.23 Y1.1@2126.74,2700.68
XTALP: C32.2 U1.D1 Y1.3 | length 264.1
  Top Layer w4: U1.D1@2006.5,2598.12 2017.45,2609.07 2017.45,2639.1 v2(2067.13,2688.78)
  Bottom Layer w4: v2(2067.13,2688.78) 2066.56,2691.19 C32.2@2082.16,2716.51 ; C32.2@2083.65,2715.59 2083.65,2717.56 2093.55,2727.46 2162.09,2727.46 2170.04,2735.41 Y1.3@2170.04,2755.8
pads on no net: Designator6_2. Designator6_3. Designator6_4. Designator6_5. Designator6_6. Designator6_7. Designator6_8. Designator6_9. FID5.1 FID6.1 FID7.1 FID8.1 FID9.1 FID10.1 FID11.1 FID12.1 FID13.1 FID14.1 FID15.1 FID16.1 FID17.1 FID18.1 J6.14 J6.15 J6.16 J6.17 J6.19 J6.20 J6.21 J6.22 J6.23 J6.25 J6.27 J6.29 J6.31 J6.32 J6.33 J6.34 J6.35 J6.37 J6.38 J6.39 J6.40 J6.41 J6.43 J6.45 J6.47 J6.49 J6.MH1 J6.MH2 J7.ALIGN J11.3 J11.6 J11.8 J11.10 J11.11 J11.12 J11.16 J12.3 J12.4 J12.5 J12.7 J12.8 J12.11 J12.15 J12.18 J12.20 J14.2 S7.MH1 S7.MH2 S8.MH1 S8.MH2 U10.7@2496.6,1111.65 U10.7@2532.04,1111.65 U11.1 U11.2 U13.2 U13.5 U13.7@2256.79,438.03 U13.7@2256.79,473.46 U20.4 U21.2 U21.3 U21.4 U21.5 U21.6 U21.11 U21.12 U21.13 U21.14 U21.15 U21.18 U21.19 U21.20 U21.21 U21.22 U21.23 U21.27 U21.29 U21.30 U21.31 U21.32 U21.41 U21.44 U21.45 U21.46 U21.49 U21.50 U21.53 U21.54 U21.56 U21.57 U21.65 U21.67 U21.71 U21.72 U21.73 U21.74 U21.75 U21.76 U21.77 U21.78 U21.81 U21.82 U21.83 U21.84 U21.85 U21.86 U21.91 U21.92 U21.97 U21.98 U21.99 U21.100 U21.102 U21.103 U21.104 U21.105 U21.106 U21.107 U21.108 U21.109 U21.110 U21.116 U21.117 U21.118 U21.119 U21.120 U21.121 U21.123 U21.124 U21.125 U21.126 U21.127 U21.128 U22.3 U23.3 U23.8 U26.6 U26.7 U27.21 U27.22 U27.23 U27.24 U27.29 U27.30 U27.33 U27.40 U27.41 U27.43 U27.44 U27.46 U27.53 U27.57 U27.58 U27.60 U28.12 U28.16 U28.22

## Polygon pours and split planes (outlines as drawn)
GND on L4_PWR1 "NONET_L08_P-001" (solid, remove dead copper, pour order 186): -0.98,3700.79 -0.98,0 1248.62,0 1248.62,381.95 1608.62,381.95 1608.62,0 3168.31,0 3168.31,3700.79
RADAR_1V_RF_OUT on L4_PWR1 "NONET_L08_P-001" (solid, remove dead copper, pour order 185): 32 vertices, not listed, extent 1383.4,2480.65 2321.85,2938.93
FTDI_3V3 on L4_PWR1 "NONET_L08_P-001" (solid, remove dead copper, pour order 163): 19 vertices, not listed, extent 1259.84,511.5 1660.39,1057.09
PMIC_OUT_3V3 on L4_PWR1 "NONET_L08_P-001" (solid, remove dead copper, pour order 167): 34 vertices, not listed, extent 520.78,1227.92 1845.13,2227.78
VCC_3V3 on L4_PWR1 "NONET_L08_P-001" (solid, remove dead copper, pour order 159): 2576.02,1971.38 2547.02,1971.38 2542.61,1966.98 2542.61,1915.95 2547.92,1910.64 2585.76,1872.8 2585.76,1863.16 2650.99,1797.93 2650.99,1645.28 2657.29,1638.98 2739,1638.98 2758.48,1658.46 2758.48,1797.63 2584.7,1971.41
VCC_XDS_3V3 on L4_PWR1 "NONET_L08_P-001" (solid, remove dead copper, pour order 174): 75 vertices, not listed, extent 858.16,470.19 2194.67,2217.57
VCC_3V3 on L4_PWR1 "NONET_L08_P-001" (solid, remove dead copper, pour order 165): 34 vertices, not listed, extent 214.63,230.88 1122.05,2760.45
RADAR_3V3 on L4_PWR1 "NONET_L08_P-001" (solid, remove dead copper, pour order 168): 21 vertices, not listed, extent 949.45,2129.22 1771.85,2647.91
5V_IN_USB on L4_PWR1 "NONET_L08_P-001" (solid, remove dead copper, pour order 155): 19 vertices, not listed, extent 2669.76,441.99 3110.74,1437.72
RADAR_1V2 on L4_PWR1 "NONET_L08_P-001" (solid, remove dead copper, pour order 184): 25 vertices, not listed, extent 1616.28,2279.15 1988.48,2537.32
VCC_3V3 on L4_PWR1 "NONET_L08_P-001" (solid, remove dead copper, pour order 162): 2461.64,1574.8 2467.75,1580.92 2467.75,1605.07 2459.64,1613.13 2370.02,1613.13 2321.88,1564.99 2321.88,1460.87 2373.33,1409.41 2411.49,1409.41 2421.61,1419.54 2421.61,1445.22 2367.65,1499.18 2367.65,1540.42 2402.03,1574.8
GND on Bottom Layer "NONET_L08_P-001" (solid, remove dead copper, pour order 203): 0,3700.79 3168.31,3700.79 3168.31,0 0,0
FTDI_3V3 on Bottom Layer "NONET_L08_P-001" (solid, remove dead copper, pour order 187): 60 vertices, not listed, extent 1110.26,411.77 1652.66,855.27
PMIC_VREG_5V0 on Bottom Layer "NONET_L08_P-001" (solid, remove dead copper, pour order 93): 1625.7,1359.58 1625.7,1290.44 1626.23,1289.92 1678.57,1289.92 1689.65,1300.99 1689.82,1300.99 1706.72,1317.89 1706.72,1359.58
VSYS_IN on Bottom Layer "NONET_L08_P-001" (solid, remove dead copper, pour order 87): 2088.14,819.46 2086.04,817.36 2086.04,751.03 2089.08,748.07 2089.08,689.49 2107.49,671.08 2169.2,671.08 2169.2,708.48 2175.35,714.63 2175.35,814.6 2170.49,819.46
VCC_XDS_3V3 on Bottom Layer "NONET_L-01_P-001" (solid, remove dead copper, pour order 138): 30 vertices, not listed, extent 1117.6,2154.01 1351.5,2319.21
GND on Bottom Layer "NONET_L08_P-001" (solid, remove dead copper, pour order 96): 33 vertices, not listed, extent 1530.96,1355.73 2202.47,1484.41
RADAR_1V_RF_OUT on Bottom Layer "RADAR_1V_RF_OUT_L08_P020" (solid, remove dead copper, pour order 20): 2046.89,2531.3 2130.14,2531.3 2130.14,2480.65 1999.84,2480.65 1994.55,2485.94 1994.55,2513.42 2012.44,2531.3
RADAR_1P2_RF on Bottom Layer "NONET_L08_P-001" (solid, remove dead copper, pour order 24): 2014.79,2399.5 2037.23,2421.94 2178.74,2421.94 2194.82,2404.03 2194.82,2267.26 2228.96,2233.12 2285.7,2233.12 2324.49,2271.91 2324.49,2469.45 2009.57,2469.45 1997.51,2457.39 1997.51,2399.5
RADAR_1V8 on Bottom Layer "Bottom Layer-RADAR_1V8" (solid, remove dead copper, pour order 21): 44 vertices, not listed, extent 1081.19,2532.76 2023.84,3237.83
VCC_XDS_3V3 on Bottom Layer "NONET_L08_P-001" (solid, remove dead copper, pour order 177): 1303.67,694.48 1323.36,694.48 1349.02,720.13 1414.71,720.13 1424.21,710.63 1480.32,710.63 1488.19,702.76 1488.19,691.93 1481.3,685.04 1417.13,685.04 1401.33,700.84 1367.82,700.84 1337.83,670.85 1303.67,670.85
VCC_3V3 on Bottom Layer "NONET_L08_P-001" (solid, remove dead copper, pour order 199): 902.6,2747.13 902.6,2763.77 886.95,2779.42 825.05,2779.42 813.78,2768.15 813.78,2600.15 884.81,2600.15 899.65,2614.99
VCC_3V3 on Bottom Layer "NONET_L08_P-001" (solid, remove dead copper, pour order 122): 2883.98,1828.99 2883.98,1809.99 2893.23,1800.73 2928.02,1800.73 2946.82,1819.53 2946.82,1935.53 2917.55,1964.81 2887.65,1964.81 2883.98,1961.13
GND on Bottom Layer "NONET_L08_P-001" (solid, remove dead copper, pour order 123): 2815.94,1806.35 2837.49,1784.8 2867.04,1784.8 2870.59,1788.34 2870.59,1831.22 2870.59,1919.29 2864.22,1925.5 2829.68,1925.5 2815.94,1911.77
FTDI_3V3 on Bottom Layer "NONET_L08_P-001" (solid, remove dead copper, pour order 180): 42 vertices, not listed, extent 1218.98,960.07 1596.46,1376.82
FTDI_3V3 on Bottom Layer "NONET_L08_P-001" (solid, remove dead copper, pour order 179): 1061.45,1382.94 1027.04,1382.94 1018.86,1374.76 1018.86,1302.33 1011.29,1294.75 1011.29,1194.97 1015.72,1190.54 1021.19,1190.54 1026.51,1195.86 1026.51,1260.51 1069.56,1303.56 1069.56,1374.83
FTDI_3V3 on Bottom Layer "NONET_L08_P-001" (solid, remove dead copper, pour order 178): 22 vertices, not listed, extent 750.32,1166.79 937.92,1402.56
VCC_XDS_3V3 on Bottom Layer "NONET_L08_P-001" (solid, remove dead copper, pour order 142): 44 vertices, not listed, extent 1037.38,1501.76 1481.43,1738.77
VCC_3V3 on Bottom Layer "NONET_L08_P-001" (solid, remove dead copper, pour order 22): 1569.28,1576.42 1567.01,1578.69 1549.02,1578.69 1540.52,1570.2 1505.99,1570.2 1502.18,1566.39 1502.18,1546.84 1508.29,1540.73 1552.22,1540.73 1569.28,1557.8
RADAR_3V3 on Bottom Layer "NONET_L08_P-001" (solid, remove dead copper, pour order 116): 1029.85,2663.11 1018.17,2674.79 948.18,2674.79 937.43,2664.03 937.43,2580.56 957.41,2560.58 1020.82,2560.58 1029.85,2569.61
VCC_XDS_3V3 on Bottom Layer "NONET_L-01_P-001" (solid, remove dead copper, pour order 139): 25 vertices, not listed, extent 847.35,1777.88 1016.3,1949.03
GND on Bottom Layer "NONET_L08_P-001" (solid, remove dead copper, pour order 25): 1707,2709.43 1711.88,2714.31 1751.1,2714.31 1764.62,2700.79 1764.62,2611.71 1775.86,2600.48 1775.86,2547.71 1735.01,2547.71 1731.57,2551.15 1731.57,2591.99 1707,2616.56
RADAR_1V2 on Bottom Layer "NONET_L08_P-001" (solid, remove dead copper, pour order 33): 38 vertices, not listed, extent 1858.94,2101.51 2026.06,2457.83
RADAR_1V2 on Bottom Layer "NONET_L08_P-001" (solid, remove dead copper, pour order 41): 1743.6,2527.7 1732.97,2538.33 1691.47,2538.33 1691.47,2508.85 1735.14,2508.85 1743.6,2517.32
GND on Bottom Layer "NONET_L08_P-001" (solid, remove dead copper, pour order 57): 1900.06,2552.57 1910.67,2552.57 1916.57,2558.47 1916.57,2568.33 1907.09,2577.81 1907.09,2597.26 1906.9,2597.45 1906.32,2597.67 1883.41,2597.67 1877.76,2592.02 1877.76,2574.87
GND on Bottom Layer "NONET_L08_P-001" (solid, remove dead copper, pour order 58): 35 vertices, not listed, extent 1768.86,2187.73 1943.9,2543.37
VSYS_IN on Bottom Layer "NONET_L08_P-001" (solid, remove dead copper, pour order 59): 2419.82,796.59 2427.8,788.61 2427.57,732.3 2419.53,724.25 2309.61,724.25 2300.44,715.08 2279.23,715.08 2272.33,721.97 2272.33,782.19 2286.73,796.59
GND on Bottom Layer "NONET_L08_P-001" (solid, remove dead copper, pour order 90): 2263.21,817.36 2207.69,817.36 2190.43,800.11 2190.43,670.3 2234.97,625.76 2425.02,625.76 2431.94,632.68 2431.94,694.08 2419.78,706.24 2274.71,706.24 2263.21,717.75 2263.21,754.37
PMIC_OUT_1V8 on Bottom Layer "NONET_L08_P-001" (solid, remove dead copper, pour order 107): 844.43,3304.47 600.26,3304.47 586.64,3290.85 586.64,3231.8 594.6,3223.84 842.84,3223.84 852.19,3233.19 852.19,3295.53
PMIC_OUT_3V3 on Bottom Layer "NONET_L08_P-001" (solid, remove dead copper, pour order 108): 1646.96,1511.69 1628.4,1511.69 1620.55,1503.83 1620.55,1465.52 1625.55,1460.53 1645.77,1460.53 1653.87,1468.62 1653.87,1503.83
REG_1V8 on Bottom Layer "NONET_L08_P-001" (solid, remove dead copper, pour order 109): 882.71,3071.89 889.03,3065.56 889.25,3065.78 1004.42,3065.78 1013.15,3074.26 1013.15,3234.83 1012.58,3235.4 1011.2,3235.97 989.4,3235.97 967.59,3257.77 967.59,3280.38 955.42,3292.56 890.95,3292.56 882.71,3284.32
GND on Bottom Layer "NONET_L08_P-001" (solid, remove dead copper, pour order 110): 794.91,3423.18 803.8,3414.29 803.8,3352.71 793.26,3342.55 584.63,3342.55 576.68,3350.51 576.68,3409.56 590.3,3423.18
GND on Bottom Layer "NONET_L08_P-001" (solid, remove dead copper, pour order 111): 722.08,3071.13 722.08,3191.57 734.64,3204.13 840.86,3204.13 841.46,3204.73 842.36,3204.73 851.06,3196.03 851.06,3094.28 819.46,3062.68 730.54,3062.68
VCC_3V3 on Bottom Layer "NONET_L08_P-001" (solid, remove dead copper, pour order 112): 1107.93,3252.87 1165.61,3252.87 1172.65,3259.92 1172.65,3305.07 1149.03,3305.07 1142.83,3311.27 1107.43,3311.27 1103.93,3307.77 1103.93,3256.87
VCC_3V3 on Bottom Layer "NONET_L08_P-001" (solid, remove dead copper, pour order 117): 969.86,2746.2 973.89,2750.24 1011.64,2750.24 1015.67,2746.2 1033.37,2746.2 1036.87,2742.71 1036.87,2691.81 1030.06,2685 978,2685 969.86,2693.15
MCU_3V3 on Bottom Layer "NONET_L08_P-001" (solid, remove dead copper, pour order 124): 347.75,2049.95 347.75,2093.08 339.87,2100.96 339.87,2138.52 380.02,2138.52 380.02,2041.42 403.31,2018.13 403.31,1978.63 401.88,1977.2 316.82,1977.2 315.34,1978.68 315.34,2017.54
VCC_3V3 on Bottom Layer "NONET_L08_P-001" (solid, remove dead copper, pour order 125): 403.2,2138.02 464.52,2138.02 473.07,2129.47 473.07,2099.55 468.12,2094.6 409.22,2094.6 403.2,2100.62
MCU_5V on Bottom Layer "NONET_L08_P-001" (solid, remove dead copper, pour order 126): 538.89,2046.54 551.87,2059.52 726.72,2059.52 735.7,2050.54 735.7,1976.8 538.89,1976.8
VSYS_IN on Bottom Layer "NONET_L08_P-001" (solid, remove dead copper, pour order 133): 757.64,2016.81 834.32,2016.81 844.74,2007 844.74,1943.72 828.32,1927.3 774.95,1927.3 757.94,1944.31
GND on Bottom Layer "NONET_L08_P-001" (solid, remove dead copper, pour order 134): 730.01,1889.95 716.49,1876.43 536.72,1876.43 536.72,1928.16 559.82,1951.26 642.44,1951.26 652.1,1960.92 718.79,1960.92 730.01,1949.7 730.01,1927.91
PMIC_OUT_3V3 on Bottom Layer "NONET_L08_P-001" (solid, remove dead copper, pour order 135): 1848.02,1503.93 1823.98,1503.93 1808.53,1488.48 1808.53,1456.71 1815.97,1449.26 1845.73,1449.26 1855.47,1459 1855.47,1496.78
PMIC_OUT_3V3 on Bottom Layer "NONET_L08_P-001" (solid, remove dead copper, pour order 137): 1800.98,1370.7 1790.21,1359.93 1790.21,1323.79 1797.96,1316.03 1839.38,1316.03 1849.12,1325.77 1849.12,1363.55 1841.67,1370.7
VBUS_1_DETECT on Bottom Layer "NONET_L08_P-001" (solid, remove dead copper, pour order 140): 1009.04,1699.23 946.69,1699.23 938.61,1707.31 914.98,1707.31 911.05,1703.38 911.05,1645.69 934.67,1645.69 934.67,1665.38 948.83,1679.53 1006.67,1679.53 1012.98,1685.84 1012.98,1697.42 1011.17,1699.23
PMIC_OUT_3V3 on Bottom Layer "NONET_L08_P-001" (solid, remove dead copper, pour order 143): 1590.16,1582.66 1584.6,1577.1 1584.6,1550.38 1591.32,1543.66 1620.56,1543.66 1622.26,1541.97 1644.37,1541.97 1652.05,1549.65 1652.05,1577.35 1646.74,1582.66
CONN_5V on Bottom Layer "NONET_L08_P-001" (solid, remove dead copper, pour order 144): 22 vertices, not listed, extent 1763.5,300.17 1991.57,650.11
GND on Bottom Layer "NONET_L08_P-001" (solid, remove dead copper, pour order 145): 1819.85,670.13 1819.85,713.7 1829.72,723.57 1889.36,723.57 1907.36,705.57 1914.29,705.57 1926.97,692.89 1926.97,656.39 1918.61,648.02 1832.22,648.02 1819.85,660.39
VSYS_IN on Bottom Layer "NONET_L08_P-001" (solid, remove dead copper, pour order 146): 1739.87,644.63 1696.49,644.63 1682.98,631.12 1683.33,630.77 1683.33,571.59 1698.04,556.88 1727.1,556.88 1739.87,569.66 1739.87,607.22
VCC_XDS_3V3 on Bottom Layer "NONET_L08_P-001" (solid, remove dead copper, pour order 176): 956.09,2124.36 952.35,2128.1 907.43,2128.1 905.78,2126.44 905.78,2102.24 929.99,2102.24 947.27,2084.95 1010.83,2084.95 1015.74,2089.86 1015.74,2122.52 1008.98,2124.36
GND on Top Layer "NONET_L08_P-001" (solid, remove dead copper, pour order 206): 1360.46,3700.79 1360.46,2444.95 1662.61,2142.8 3168.31,2142.8 3168.31,0 -0.98,0 -0.98,3700.79
GND on Top Layer "NONET_L08_P-001" (solid, remove dead copper, pour order 202): 3156.07,2164.14 3147.41,2155.48 1689.61,2155.48 1414.79,2430.31 1414.79,3681.79 1421.54,3688.54 1438.41,3688.54 cw(c1439,3669.23) 1439.02,3688.55 3125,3688.55 cw(c3125.01,3657.48) 3156.07,3657.48
VSYS_IN on Top Layer "NONET_L08_P-001" (solid, remove dead copper, pour order 61): 18 vertices, not listed, extent 1596.32,1059.73 1722.46,1359.15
